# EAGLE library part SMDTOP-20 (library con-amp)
AMP connector
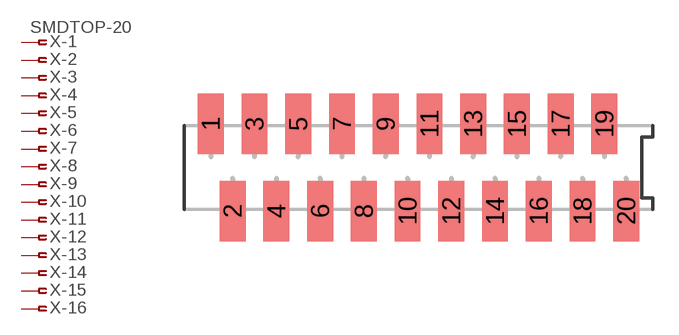
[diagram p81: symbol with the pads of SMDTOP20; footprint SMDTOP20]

Designator prefix X; gates -1=PIN-FV -2=PIN-F -3=PIN-F -4=PIN-F -5=PIN-F -6=PIN-F -7=PIN-F -8=PIN-F -9=PIN-F -10=PIN-F -11=PIN-F -12=PIN-F -13=PIN-F -14=PIN-F -15=PIN-F -16=PIN-F -17=PIN-F -18=PIN-F -19=PIN-F -20=PIN-F

## SMDTOP-20 (OC_FARNELL: unknown; OC_NEWARK: unknown)  [SMDTOP20]
1  -1:1  pas
2  -2:1  pas
3  -3:1  pas
4  -4:1  pas
5  -5:1  pas
6  -6:1  pas
7  -7:1  pas
8  -8:1  pas
9  -9:1  pas
10  -10:1  pas
11  -11:1  pas
12  -12:1  pas
13  -13:1  pas
14  -14:1  pas
15  -15:1  pas
16  -16:1  pas
17  -17:1  pas
18  -18:1  pas
19  -19:1  pas
20  -20:1  pas

## Footprint SMDTOP20 (pad centres in mm)
AMP connector
smd 1.5 x 3.5: 1 -12.065,2.54; 2 -10.795,-2.54; 3 -9.525,2.54; 4 -8.255,-2.54; 5 -6.985,2.54; 6 -5.715,-2.54; 7 -4.445,2.54; 8 -3.175,-2.54; 9 -1.905,2.54; 10 -0.635,-2.54; 11 0.635,2.54; 12 1.905,-2.54; 13 3.175,2.54; 14 4.445,-2.54; 15 5.715,2.54; 16 6.985,-2.54; 17 8.255,2.54; 18 9.525,-2.54; 19 10.795,2.54; 20 12.065,-2.54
